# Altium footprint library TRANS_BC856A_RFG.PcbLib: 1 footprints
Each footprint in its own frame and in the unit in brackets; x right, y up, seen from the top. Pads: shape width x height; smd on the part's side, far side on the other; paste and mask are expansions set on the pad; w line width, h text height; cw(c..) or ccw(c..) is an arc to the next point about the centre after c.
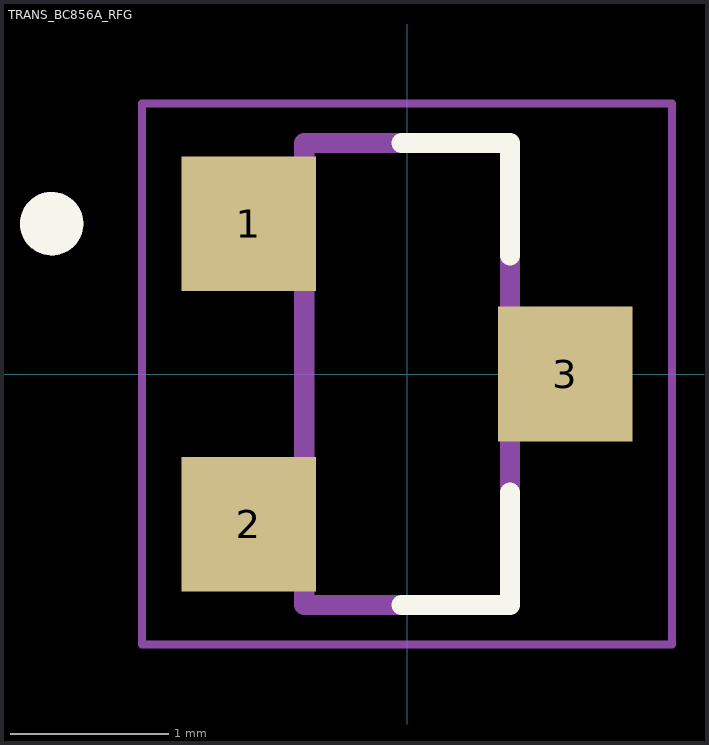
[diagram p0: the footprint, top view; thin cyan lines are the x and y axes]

## TRANS_BC856A_RFG [mm]
height 1.12
pads (3):
  rect 0.85x0.85 smd: 1(-1,0.95) 2(-1,-0.95) 3(1,0)
Top Overlay:
  circle w0.2: c-2.246,0.95 r0.1
  lines w0.127: -0.035,-1.46 0.65,-1.46 0.65,-0.75 ; -0.035,1.46 0.65,1.46 0.65,0.75
Mechanical 13:
  circle w0.2: c-2.246,0.95 r0.1
  lines w0.127: -0.65,-1.46 -0.65,1.46 0.65,1.46 0.65,-1.46 -0.65,-1.46
Mechanical 15:
  lines w0.05: -1.675,-1.71 -1.675,1.71 1.675,1.71 1.675,-1.71 -1.675,-1.71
